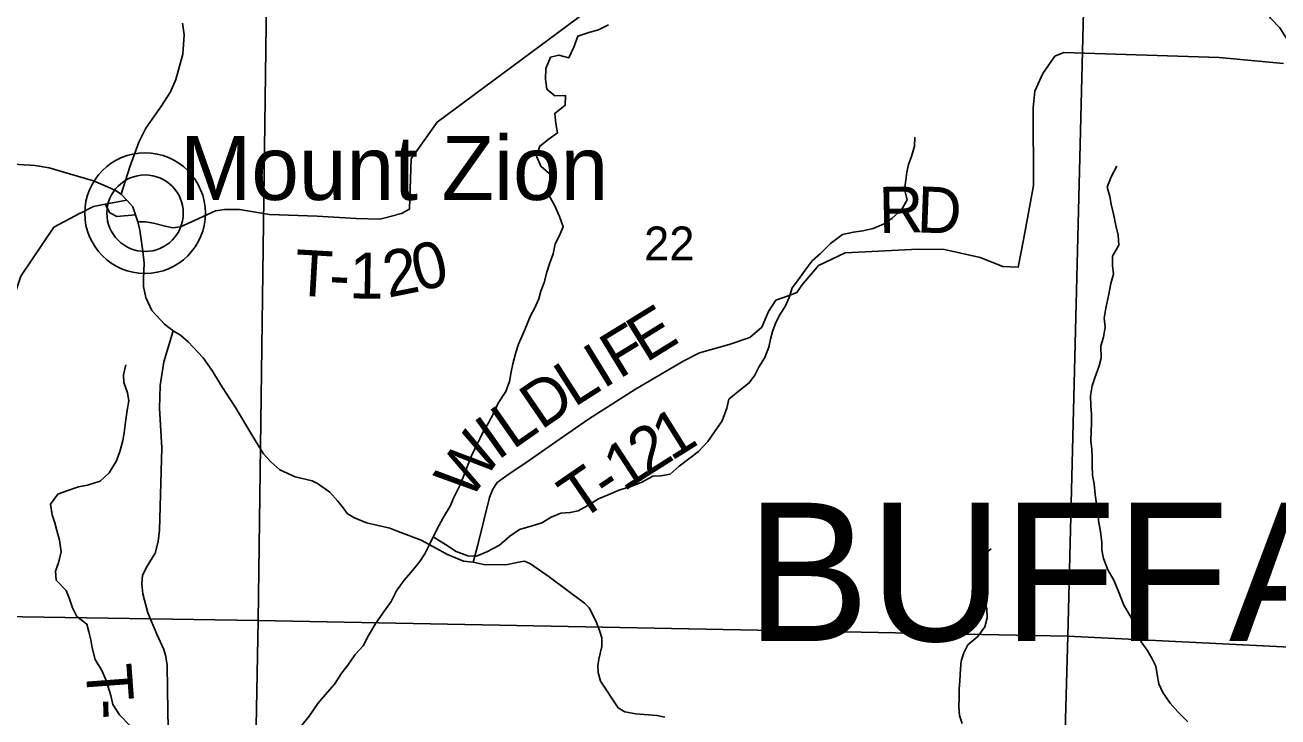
# Model space of a CAD drawing. Extents: x 2043100 to 2470832, y 443715 to 810583.
# Drawn here: x 2241363 to 2249519, y 681017 to 685521 of the extents above; entities that cross this region are included whole.
import ezdxf

# ---------------------------------------------------------------- set-up
doc = ezdxf.new("R2010")
doc.units = 0
for name, color, linetype in [('GM_X_County_Road', 7, 'Continuous'), ('GM_X_Minor_River', 7, 'Continuous'), ('GM_X_Section', 7, 'Continuous'), ('GM_X_Section_Text', 7, 'Continuous'), ('GM_X_Township_Road', 7, 'Continuous'), ('GM_X_Township_Road_Text', 7, 'Continuous'), ('GM_X_Township_ROW', 7, 'Continuous'), ('GM_X_Township_Text', 7, 'Continuous'), ('GM_X_Unincorporated', 7, 'Continuous'), ('GM_X_Unincorporated_Location', 7, 'Continuous'), ('GM_X_Unincorporated_Text', 7, 'Continuous')]:
    doc.layers.add(name, color=color, linetype=linetype)

msp = doc.modelspace()

# ---------------------------------------------------------------- linework, layer by layer
at = {"layer": 'GM_X_County_Road'}
for points in [[(2240159.3, 685351.7), (2240182.6, 685287.4), (2240211.7, 685199.1), (2240238.9, 685134.7), (2240278.2, 685068.3), (2240347.5, 685009.6), (2240476.5, 684942.3), (2240641.4, 684864.6), (2240804.4, 684795), (2241044.8, 684682.5), (2241140.2, 684641.6), (2241197.9, 684627), (2241323.6, 684613.8), (2241429.3, 684606.7), (2241518.9, 684591.8), (2241652.3, 684552.5), (2241807.5, 684506.9), (2241898.9, 684468), (2241952.6, 684443.5), (2241989.1, 684420), (2242025.2, 684381.3), (2242065.3, 684338.3), (2242081.6, 684286.2), (2242096.3, 684239.2)], [(2242096.3, 684239.2), (2242109.2, 684185.4), (2242129.5, 684049.5), (2242138.9, 683971.6), (2242134.7, 683869.4), (2242133.5, 683819.3), (2242148.8, 683747.5), (2242188.2, 683662.1), (2242271.8, 683573.5), (2242326.5, 683530.4), (2242375, 683501.2), (2242425.7, 683458.1), (2242523.5, 683353.7), (2242578.9, 683274.6), (2242648.8, 683161.7), (2242733, 683031), (2242846.3, 682842.8), (2242916.2, 682729.9), (2242963.1, 682676.6), (2243022, 682625.6), (2243120.8, 682579.3), (2243231.2, 682553.3), (2243267.5, 682535.9), (2243346.5, 682479.3), (2243399.5, 682422.1), (2243434.2, 682378.7), (2243462.9, 682339.2), (2243507.4, 682311.9), (2243585.9, 682281.3), (2243738.5, 682246), (2243792.8, 682224.9), (2243941.8, 682167.5), (2244113.4, 682074.5), (2244218.1, 682030.3), (2244280.2, 682023.4), (2244358.5, 682006.8), (2244504.4, 682009.4), (2244586.1, 682026.9), (2244614, 682031.4), (2244654.3, 682014.1), (2244773.8, 681928.1), (2245004.7, 681758.1), (2245035.2, 681726.6), (2245078.7, 681643.2), (2245103.9, 681573.6), (2245116.6, 681531.8), (2245117.6, 681475.7), (2245099, 681393.3), (2245091.8, 681349.1), (2245094.5, 681307.1), (2245109.5, 681249.2), (2245224.4, 681077.1), (2245266.9, 681049.8), (2245339.1, 681037.1), (2245475.3, 681025.5), (2245527.4, 681016.4)]]:
    msp.add_lwpolyline(points, dxfattribs=at)
at = {"layer": 'GM_X_Minor_River'}
for points in [[(2250263.9, 684895.8), (2250210.9, 684942.5), (2250150.6, 685004.3), (2250080.4, 685051.9), (2250016.2, 685099.6), (2249950, 685127.3), (2249898, 685133), (2249829.9, 685148.6), (2249757.9, 685164.2), (2249691.8, 685181.8), (2249645.5, 685243.7), (2249635.1, 685319.7), (2249608.7, 685389.6), (2249568.4, 685443.5), (2249530.1, 685503.3), (2249469.8, 685565.1), (2249433.4, 685632.9), (2249373.1, 685694.7), (2249323, 685726.4)], [(2244764.8, 684428.5), (2244770.6, 684476.8), (2244786.7, 684544.8), (2244720.9, 684601), (2244693.1, 684667), (2244713.2, 684733.1), (2244775.2, 684781), (2244829.2, 684819), (2244817.3, 684879), (2244811.4, 684945.1), (2244879.4, 684999), (2244881.5, 685061), (2244811.6, 685059.1), (2244759.8, 685103.2), (2244750, 685167.3), (2244754.1, 685237.3), (2244784.2, 685311.3), (2244838.1, 685325.3), (2244902, 685307.2), (2244936.1, 685377.2), (2244962.1, 685449.2), (2245032.1, 685473.1), (2245096, 685489), (2245160, 685523)], [(2247088.9, 684452.5), (2247096.8, 684511.6), (2247102.9, 684563.6), (2247112.9, 684613.6), (2247133, 684665.6), (2247153.1, 684731.7), (2247155.2, 684791.7)], [(2248406.8, 684466.1), (2248432.6, 684531.7), (2248470.6, 684601.7)], [(2244020.6, 682189.6), (2244100.7, 682140), (2244168.8, 682094.2), (2244244.8, 682064.5), (2244302.8, 682062.7), (2244368.7, 682090.9), (2244452.5, 682135.2), (2244518.3, 682193.5), (2244582.2, 682237.8), (2244664.1, 682260), (2244728, 682280.3), (2244787.9, 682316.5), (2244851.8, 682342.7), (2244911.7, 682346.9), (2244963.7, 682359.1), (2245027.5, 682393.4), (2245095.4, 682435.6), (2245159.3, 682461.9), (2245235.2, 682494.2), (2245301.1, 682514.4), (2245373, 682542.7), (2245448.8, 682584.9), (2245500.8, 682587.1), (2245562.7, 682597.3), (2245620.5, 682649.6), (2245692.4, 682703.9), (2245746.2, 682744.1), (2245808, 682810.3), (2245851.8, 682872.5), (2245901.6, 682944.7), (2245931.3, 683026.9), (2245945.1, 683085), (2246016.9, 683143.3), (2246076.8, 683191.5), (2246114.6, 683241.7), (2246142.4, 683297.8), (2246178.2, 683356), (2246204, 683424.1), (2246215.9, 683476.2), (2246227.7, 683526.2), (2246249.5, 683584.4), (2246279.4, 683638.5), (2246311.2, 683688.7), (2246337, 683746.8), (2246356.8, 683810.9), (2246398.6, 683865.1), (2246440.5, 683925.2), (2246486.3, 683985.4), (2246540.1, 684033.7), (2246605.9, 684097.9), (2246683.7, 684156.2), (2246755.6, 684172.5), (2246815.6, 684180.7), (2246883.5, 684196.9), (2246955.4, 684227.2), (2247007.2, 684263.4), (2247069, 684317.7), (2247104.8, 684383.8), (2247088.9, 684452.5)], [(2248932.1, 680985.7), (2248867.9, 681049.5), (2248817.8, 681107.4), (2248769.6, 681175.3), (2248743.5, 681233.2), (2248733.3, 681293.2), (2248723.1, 681347.2), (2248697, 681399.2), (2248666.8, 681451.1), (2248628.7, 681505), (2248604.6, 681557), (2248592.4, 681607), (2248556.2, 681674.9), (2248516, 681744.8), (2248481.8, 681832.8), (2248451.6, 681906.7), (2248411.4, 681974.6), (2248383.2, 682048.6), (2248373, 682102.6), (2248372.9, 682152.6), (2248364.7, 682224.6), (2248350.5, 682294.6), (2248348.3, 682352.7), (2248338.2, 682404.7), (2248328, 682464.7), (2248321.8, 682534.7), (2248311.6, 682588.7), (2248309.4, 682652.7), (2248309.3, 682704.8), (2248307.1, 682756.8), (2248301, 682814.8), (2248302.8, 682876.9), (2248304.6, 682926.9), (2248304.5, 682986.9), (2248300.3, 683043), (2248298.1, 683107), (2248309.9, 683171.1), (2248327.8, 683223.2), (2248355.5, 683301.3), (2248367.4, 683351.4), (2248365.1, 683433.5), (2248383, 683489.6), (2248394.8, 683553.6), (2248388.6, 683611.7), (2248398.4, 683677.7), (2248418.1, 683767.9), (2248431.9, 683838), (2248447.7, 683898.1), (2248441.6, 683956.1), (2248441.4, 684016.1), (2248483.2, 684088.3), (2248479, 684152.3), (2248462.8, 684216.3), (2248450.6, 684280.3), (2248432.4, 684354.3), (2248424.2, 684404.3), (2248406.8, 684466.1)], [(2243158.5, 680954), (2243212.3, 681022.2), (2243268, 681104.5), (2243317.9, 681162.7), (2243377.6, 681230.9), (2243425.4, 681303.2), (2243465.2, 681353.3), (2243511, 681423.5), (2243564.8, 681479.8), (2243598.6, 681547.9), (2243646.4, 681628.1), (2243702.1, 681708.4), (2243745.9, 681768.6), (2243781.7, 681836.7), (2243831.5, 681907), (2243875.3, 681957.1), (2243933.1, 682029.4), (2243964.9, 682079.5), (2244000.7, 682147.7), (2244024.5, 682197.8), (2244058.3, 682266), (2244086.1, 682318.1), (2244129.9, 682388.3), (2244151.7, 682440.4), (2244193.5, 682522.6), (2244223.3, 682598.8), (2244243.1, 682650.9), (2244268.9, 682717), (2244292.7, 682767.1), (2244322.5, 682827.3), (2244348.4, 682877.4), (2244378.2, 682927.5), (2244414, 682995.7), (2244443.8, 683059.8), (2244493.6, 683136.1), (2244517.4, 683200.2), (2244527.2, 683262.3), (2244539, 683314.3), (2244558.8, 683388.5), (2244574.6, 683442.6), (2244606.4, 683512.7), (2244630.2, 683568.8), (2244650.1, 683622.9), (2244681.9, 683679.1), (2244707.7, 683739.2), (2244721.6, 683789.3), (2244741.4, 683845.4), (2244759.2, 683911.5), (2244777, 683965.6), (2244800.8, 684031.8), (2244814.6, 684095.8), (2244840.5, 684145.9), (2244866.3, 684206.1), (2244842.1, 684274), (2244809.9, 684348), (2244764.8, 684428.5)], [(2242045, 680962.2), (2241978.8, 681030), (2241934.6, 681097.9), (2241922.4, 681155.9), (2241890.2, 681253.9), (2241862, 681319.8), (2241819.8, 681391.8), (2241799.6, 681467.7), (2241791.4, 681519.7), (2241777.3, 681571.7), (2241765.1, 681621.7), (2241701, 681671.5), (2241670.8, 681727.5), (2241652.7, 681785.4), (2241630.5, 681839.4), (2241566.4, 681907.2), (2241562.2, 681965.3), (2241580, 682019.4), (2241597.8, 682091.5), (2241587.6, 682167.5), (2241569.4, 682229.5), (2241557.3, 682279.5), (2241539.1, 682331.4), (2241528.9, 682401.5), (2241576.7, 682467.7), (2241634.6, 682487.9), (2241710.5, 682514.2), (2241770.5, 682526.4), (2241852.3, 682550.7), (2241910.2, 682604.9), (2241957.9, 682683.1), (2241981.7, 682751.2), (2241999.5, 682815.3), (2242007.4, 682865.4), (2242017.1, 682935.5), (2242026.9, 683013.6), (2242038.7, 683073.7), (2242030.6, 683125.7), (2242006.4, 683193.6), (2242004.2, 683243.7), (2242018.1, 683309.8)], [(2247462.7, 680974.7), (2247446.6, 681026.7), (2247442.4, 681082.7), (2247444.2, 681144.7), (2247444.1, 681196.8), (2247447.9, 681254.8), (2247451.7, 681328.9), (2247457.5, 681380.9), (2247473.4, 681435), (2247501.2, 681485.2), (2247565, 681539.4), (2247610.8, 681603.6), (2247626.6, 681661.7), (2247624.5, 681719.8), (2247608.3, 681787.7), (2247588.1, 681857.7), (2247567.9, 681919.7), (2247561.7, 681989.7), (2247581.5, 682053.8), (2247651.3, 682112.1)]]:
    msp.add_lwpolyline(points, dxfattribs=at)
at = {"layer": 'GM_X_Section'}
for points in [[(2237595.1, 686915.4), (2242950.3, 686817), (2242879.6, 681645.2), (2237434.5, 681728.7)], [(2242950.3, 686817), (2248278.2, 686650.2), (2248150.8, 681542), (2242879.6, 681645.2)], [(2248278.2, 686650.2), (2253769.2, 686495.2), (2253630.3, 681270.6), (2248150.8, 681542)], [(2237434.5, 681728.7), (2242879.6, 681645.2), (2242780.6, 676346), (2237342.8, 676305.5)], [(2242879.6, 681645.2), (2248150.8, 681542), (2248002, 676220.2), (2242780.6, 676346)], [(2248150.8, 681542), (2253630.3, 681270.6), (2253436.7, 675966.1), (2248002, 676220.2)]]:
    msp.add_lwpolyline(points, close=True, dxfattribs=at)
at = {"layer": 'GM_X_Township_Road'}
for points in [[(2242388.7, 685532.1), (2242398, 685456), (2242390.7, 685331.9), (2242345.1, 685166.2), (2242310.4, 685086.5), (2242247.5, 684989), (2242148.3, 684849.9), (2242103.5, 684758.3), (2242046, 684596.7), (2241989.1, 684420)], [(2244840.3, 682823.4), (2245030, 682956.1), (2245336.6, 683149.9), (2245651.4, 683333.8), (2245752.5, 683387.7), (2245947.5, 683441.3), (2246080.7, 683487.7), (2246159.5, 683553.2), (2246201.8, 683656.1), (2246250.5, 683729.1), (2246337.9, 683760.7), (2246387.6, 683779.6), (2246418.8, 683828.2), (2246528.6, 683954.4), (2246701.1, 684037.6), (2247176.6, 684062.2), (2247348.6, 684059.2), (2247581.5, 684007.4), (2247728.5, 683949.9), (2247828.6, 683943.7), (2247863.5, 684122.6), (2247927.2, 684475.2), (2247926.3, 684981.6), (2247935.4, 685089.6), (2247988.4, 685205.2), (2248067.4, 685318.5), (2248125.5, 685342), (2249135.2, 685310.1), (2249556, 685271.1)], [(2242025.2, 684381.3), (2241885.5, 684354.8), (2241808.6, 684340.2), (2241724, 684295.9), (2241722.5, 684295.1)], [(2241885.5, 684354.8), (2241915.6, 684299.2), (2241959.6, 684273.6), (2242081.6, 684286.2)], [(2242096.3, 684239.2), (2242146.3, 684240.1), (2242198.4, 684231), (2242274.8, 684210.4), (2242324.9, 684201.2), (2242374.8, 684206.2), (2242470, 684249.9), (2242603, 684310.4), (2242660.8, 684319.4), (2242758.8, 684319.2), (2242953.3, 684286.6), (2243265.5, 684276.2), (2243517.7, 684260.7), (2243671.7, 684257.5), (2243782.8, 684286.2), (2243783.9, 684286.5)], [(2242307.4, 680347.7), (2242293.3, 681052.4), (2242288.1, 681352.7), (2242279.1, 681410.7), (2242266.3, 681456.5), (2242220.6, 681555.8), (2242162.2, 681694.9), (2242130.1, 681818.5), (2242123, 681882.5), (2242128, 681940.7), (2242157, 681997.3), (2242209.5, 682082.3), (2242230.2, 682158.8), (2242238.9, 682233), (2242253.7, 682768), (2242239.2, 683026.1), (2242242.6, 683174.4), (2242266, 683329), (2242326.5, 683530.4)], [(2244280.2, 682023.4), (2244308.4, 682128.1), (2244386.9, 682445.9), (2244408, 682500.4), (2244437.2, 682542.9), (2244514.3, 682598.4), (2244597.3, 682654), (2244704, 682728), (2244839.5, 682822.8), (2244840.3, 682823.4)]]:
    msp.add_lwpolyline(points, dxfattribs=at)
at = {"layer": 'GM_X_Township_ROW'}
for points in [[(2243783.9, 684286.5), (2243813.1, 684294.1), (2243866.6, 684323.1), (2243876.9, 684648.9), (2244045, 684889.4), (2245923.4, 686282.2), (2246792.9, 687192.5), (2248291, 688073.9), (2251041.3, 688930.7)], [(2241722.5, 684295.1), (2241550.9, 684205.4), (2241336.5, 683885.1), (2241094.9, 683171.8), (2240976.9, 682472.7), (2240790, 681718.3), (2240652.6, 681567.7), (2240411.1, 681425.1), (2239938, 681236.2)]]:
    msp.add_lwpolyline(points, dxfattribs=at)
at = {"layer": 'GM_X_Unincorporated'}
for radius in [392.8, 249]:
    msp.add_circle((2242144.2, 684295.8), radius, dxfattribs=at)
at = {"layer": 'GM_X_Unincorporated_Location'}
msp.add_line((2242144.2, 684295.8), (2242144.2, 684295.8), dxfattribs=at)

# ---------------------------------------------------------------- texts
at = {"layer": 'GM_X_Section_Text'}
msp.add_text('22', height=220.83, rotation=0.00001, dxfattribs=at).set_placement((2245392.4, 683988.2))
at = {"layer": 'GM_X_Township_Road_Text'}
for s, rotation, p in [('R', 1.13195, (2246923.4, 684166.6)), ('D', 357.88308, (2247165.2, 684171.5)), ('0', 13.70647, (2243921, 683784.2)), ('T', 356.71533, (2243111.6, 683761.3)), ('1', 359.08443, (2243472.2, 683741.7)), ('2', 11.29512, (2243726.3, 683745)), ('-', 357.1164, (2243337.9, 683748.3)), ('E', 31.83855, (2245405.2, 683319.8)), ('F', 31.40704, (2245230.3, 683213.1)), ('I', 31.50727, (2245125.4, 683148.8)), ('L', 32.59051, (2244937.6, 683028.7)), ('D', 34.29932, (2244721.5, 682881.2)), ('I', 35.36164, (2244438.2, 682682.3)), ('L', 34.91794, (2244538.2, 682753.3)), ('1', 31.98662, (2245567.9, 682678.8)), ('W', 54.96468, (2244257.7, 682416.8)), ('2', 32.32311, (2245412.2, 682580.2)), ('1', 33.08386, (2245258.2, 682479.9)), ('T', 34.41515, (2244972.3, 682285.5)), ('-', 33.82863, (2245156.7, 682411.9)), ('T', 274.29386, (2241755.2, 681350.4)), ('-', 271.10066, (2241771.8, 681131.1))]:
    msp.add_text(s, height=300, rotation=rotation, dxfattribs=at).set_placement(p)
at = {"layer": 'GM_X_Township_Text'}
msp.add_text('BUFFALO', height=900, rotation=0.00001, dxfattribs=at).set_placement((2246057.1, 681511.2))
at = {"layer": 'GM_X_Unincorporated_Text'}
msp.add_text('Mount Zion', height=416.67, rotation=0.00001, dxfattribs=at).set_placement((2242371.8, 684382.1))

doc.saveas('drawing.dxf')
